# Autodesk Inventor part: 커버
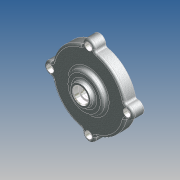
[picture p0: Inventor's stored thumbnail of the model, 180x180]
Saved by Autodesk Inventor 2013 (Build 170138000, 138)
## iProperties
Company: 한국ATC센터
Created: 2014-07
Part Number: 커버
Document SubType Name: 모델링
Designer: KYOUNG IL JANG
Material: 알루미늄 6061
Density: 1 g/cm^3
변환 표준: STEP AP214IS
파일 이름: C:\Users\SeoGD\Desktop\?쒗뿕\而ㅻ쾭-1.stp
전처리기: Build: 253, Release: 2010 SP1 - Date: Wed 07/29/2009
전송 단위: 밀리미터
불확실성: 0.01
Author: KYOUNG IL JANG
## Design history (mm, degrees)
sketch "스케치1"
  geometry: L1 (0, 0)-(0, 26); L2 (50, 0)-(50, 15); L3 (50, 15)-(25, 15); L4 (25, 15)-(25, 21); L5 (25, 21)-(15, 21); L6 (15, 21)-(13.66, 26); L7 (13.66, 26)-(10, 26); L8 (50, 0)-(45, 0); L9 (45, 0)-(45, 10); L10 (45, 10)-(14.5, 10); L11 (14.5, 10)-(13.266, 3); L12 (13.266, 3)-(11, 3); L13 (11, 3)-(11, 16); L14 (11, 16)-(7.5, 16); L15 (7.5, 16)-(7.5, 19); L16 (7.5, 19)-(10, 19); L17 (10, 19)-(10, 26)
  constraints: 34 end point, 10 parallel, 2 perpendicular, 2 point on line, 1 vertical
  dimensions: "d11" = 100 diameter of L2 L1; "d12" = 22 diameter of L13 L1; "d13" = 90 diameter of L9 L1; "d14" = 15 distance between parallel lines of L3 L8; "d15" = 10 distance between parallel lines of L8 L10; "d16" = 29 diameter of L10.end L1; "d17" = 100 deg angle of L11 L10; "d18" = 7 distance between parallel lines of L12 L10; "d19" = 13 distance between parallel lines of L14 L12; "d20" = 3 distance between parallel lines of L16 L14; "d21" = 15 diameter of L15 L1; "d22" = 20 diameter of L17 L1; "d23" = 30 diameter of L5.end L1; "d24" = 6 distance between parallel lines of L5 L3; "d25" = 50 diameter of L4 L1; "d26" = 105 deg angle of L5 L6; "d50" = 26 distance of L1.start L1.end
revolve "회전1" sketch "스케치1" stored, may be unused: angle "d27" = 90 deg
sketch "스케치2" dims "d29" = 104
  geometry: A1 r 8.5 centre (0, 52) between (8.074, 49.344) and (-8.074, 49.344); A2 r 50 centre (0, 0) between (-8.074, 49.344) and (8.074, 49.344) reference; 2 further points
  constraints: 4 point on circle, 2 vertical alignment, 1 centre point, 1 coincident, 2 other
  dimensions: "d28" = 17 diameter of A1
extrude "돌출1" join sketch "스케치2" stored distance "d30" = 10; taper "d31" = 0 deg
fillet "모깎기3" dims "d32" = 3
fillet "모깎기4" dims "d45" = 3, "d46" = 0.2
chamfer "모따기1" distance "d47" = 1; stored, may be unused: second distance "d48" = 2, angle "d49" = 45 deg
hole "구멍2" diameter "d38" = 5.5; stored, may be unused: countersink angle "d42" = 90 deg, drill point angle "d44" = 118 deg; dims "d36" = 10, "d37" = 10, "d39" = 6, "d40" = 9.5, "d41" = 5.4, "d43" = 8
node "솔리드1"
node "솔리드 본체"
node "곡면 본체"
pattern_circular "원형 패턴1" dims angle "d34" = 360 deg
pattern_circular "원형 패턴2" dims angle "d52" = 360 deg
node "솔리드2"
